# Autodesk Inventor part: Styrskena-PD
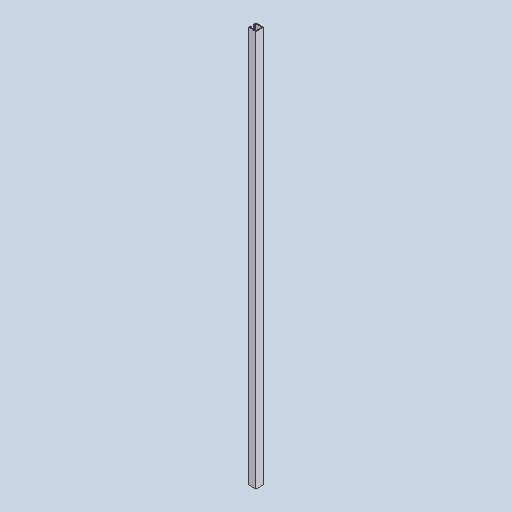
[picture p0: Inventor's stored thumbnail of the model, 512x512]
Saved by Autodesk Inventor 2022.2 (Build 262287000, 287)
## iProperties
Created: 2019-06
Part Number: Styrskena-PD
Material: Aluminum 6061, Welded
Document SubType Name: Modeling
Designer: cl
Density: 2.7 g/cm^3
Appearance: Weld - Aluminum
Author: cl
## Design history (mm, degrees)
sketch "Sketch1"
  geometry: L1 (0, 0)-(50, 0); L2 (50, 0)-(50, -15); L3 (50, -35)-(50, -50); L4 (50, -50)-(0, -50); L5 (0, -50)-(0, 0); L6 (50, -15)-(45, -15); L7 (45, -15)-(45, -5); L8 (45, -5)-(5, -5); L9 (5, -5)-(5, -45); L10 (5, -45)-(45, -45); L11 (45, -45)-(45, -35); L12 (45, -35)-(50, -35)
  constraints: 24 end point, 7 perpendicular, 4 point on line, 2 horizontal, 1 parallel
  dimensions: "d0" = 50 distance of L1.start L1.end; "d1" = 15 distance of L1.end L2.end; "d2" = 15 distance of L3.start L3.end; "d3" = 50 distance of L4.end L1.start; "d5" = 5 distance of L2.end L6.end; "d6" = 10 distance of L6.end L7.end; "d7" = 10 distance of L10.end L11.end; "d9" = 5 distance between parallel lines of L5 L9
extrude "Extrusion1" new body sketch "Sketch1" distance "d10" = 2656.66667 (computed from BladBredd); taper "d11" = 0 deg
body "Solid1"
other parameters: "BladBredd" = 1333.33333, "Fönsterhöjd" = 862, "Blad2" = 1358.33333, "Blad3" = 0, "Blad4" = 0, "Blad5" = 0, "Blad6" = 2025, "MGJ12Djup" = 0, "MGJ12Bredd" = 0, "MGJ2Djup" = 0, "MGJ2Bredd" = 5012.5, "MGJ56Djup" = 48, "MGJ23Djup" = 48, "MGJ45Djup" = 48, "GarageRegel5" = 0, "GarageRegel6" = 0
